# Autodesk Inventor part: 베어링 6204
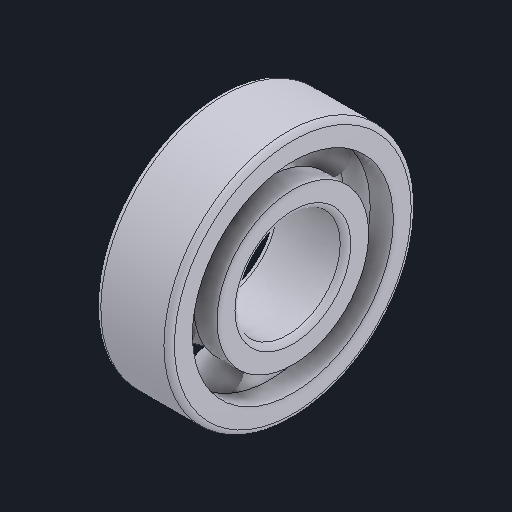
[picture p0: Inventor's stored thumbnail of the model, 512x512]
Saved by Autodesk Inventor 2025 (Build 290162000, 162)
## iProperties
Created: 2025-08
Part Number: 베어링 6204
Material: 강철, 연강
Description: 깊은 그루브 볼 베어링
Document SubType Name: Modeling
Designer: infra012
Density: 7.86 g/cm^3
Appearance: 기본값
Author: jhkim
Sending System: Autodesk Inventor 2026
Preprocessor: ST-DEVELOPER v20.1
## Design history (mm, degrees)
sketch "스케치1"
  geometry: 1 further point
feature "Solid1"
feature "Solid1:1"
feature "Solid1:2"
feature "Solid1:3"
feature "Solid1:4"
feature "Solid1:5"
feature "Solid1:6"
feature "Solid1:7"
feature "Solid1:8"
node "솔리드1"
node "솔리드2"
node "솔리드3"
node "솔리드4"
node "솔리드5"
node "솔리드6"
node "솔리드7"
node "솔리드8"
node "솔리드9"
